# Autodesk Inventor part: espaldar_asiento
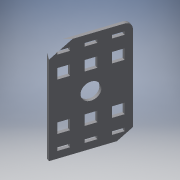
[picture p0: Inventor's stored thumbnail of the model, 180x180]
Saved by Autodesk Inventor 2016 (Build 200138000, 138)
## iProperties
Created: 2017-06
Part Number: espaldar_asiento
Material: Generic
Document SubType Name: Modeling
Designer: laboratorioesan
Density: 1 g/cm^3
Appearance: Default
Author: laboratorioesan
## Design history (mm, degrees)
sketch "Sketch1"
  geometry: L1 (0, 0)-(490, 0) reference; L2 (490, 0)-(490, 18.5) reference; L3 (0, 18.5)-(490, 18.5) reference; L4 (0, 0)-(0, 18.5) reference; L5 (854, -205.5)-(854, -75.5) reference; L6 (872.5, -75.5)-(872.5, -205.5) reference; L7 (872.5, -75.5)-(854, -75.5) reference; L8 (854, -205.5)-(854, -75.5) reference; L9 (872.5, -205.5)-(854, -205.5) reference; L10 (490, 18.5)-(613.607, 398.923); L11 (613.607, 398.923)-(631.201, 393.206); L12 (631.201, 393.206)-(507.595, 12.783); L13 (490, 18.5)-(507.595, 12.783)
  constraints: 8 end point, 3 perpendicular
  dimensions: "d0" = 18.5 distance of L10.end L11.end; "d1" = 18 deg angle of L2 L10; "d2" = 400 distance of L2.end L10.end
extrude "Extrusion1" new body sketch "Sketch1" distance "d3" = 600; taper "d4" = 0 deg
fillet "Fillet1" dims "d5" = 40
sketch "Sketch2"
  geometry: L1 (40, 400)-(560, 400) reference; L2 (0, 0)-(0, 360) reference; L3 (0, 0)-(600, 0) reference; L4 (600, 360)-(600, 0) reference; L5 (40, 360)-(58.5, 360); L6 (58.5, 360)-(58.5, 300); L7 (58.5, 300)-(40, 300); L8 (40, 300)-(40, 360); L9 (40, 230)-(58.5, 230); L10 (58.5, 230)-(58.5, 170); L11 (58.5, 170)-(40, 170); L12 (40, 170)-(40, 230); L13 (40, 100)-(58.5, 100); L14 (58.5, 100)-(58.5, 40); L15 (58.5, 40)-(40, 40); L16 (40, 40)-(40, 100); L17 (300, 400)-(300, 360); L18 (541.5, 170)-(560, 170); L19 (541.5, 230)-(541.5, 170); L20 (560, 170)-(560, 230); L21 (560, 230)-(541.5, 230); L22 (541.5, 300)-(560, 300); L23 (541.5, 360)-(541.5, 300); L24 (560, 300)-(560, 360); L25 (560, 360)-(541.5, 360); L26 (541.5, 100)-(541.5, 40); L27 (541.5, 40)-(560, 40); L28 (560, 40)-(560, 100); L29 (560, 100)-(541.5, 100); A1 r 40 centre (560, 360) between (600, 360) and (560, 400) reference; A2 r 40 centre (40, 360) between (40, 400) and (0, 360) reference; 2 further points
  constraints: 50 end point, 13 symmetric about line, 6 parallel, 4 point on line, 3 horizontal, 3 perpendicular, 1 midpoint, 1 vertical
  dimensions: "d6" = 18.5 distance of L6.end L7.end; "d7" = 60 distance of L5.end L6.end; "d8" = 40 distance between parallel lines of L1 L5; "d9" = 60 distance of L9.end L10.end; "d10" = 60 distance of L13.end L14.end; "d11" = 70 distance between parallel lines of L7 L9; "d12" = 70 distance between parallel lines of L13 L11
extrude "Extrusion2" cut sketch "Sketch2" distance "d13" = 18.5; taper "d14" = 0 deg
sketch "Sketch3"
  geometry: L1 (58.5, 300)-(40, 300) reference; L2 (40, 300)-(40, 360) reference; L3 (40, 360)-(58.5, 360) reference; L4 (58.5, 360)-(58.5, 300) reference; L5 (560, 100)-(560, 40) reference; L6 (560, 40)-(541.5, 40) reference; L7 (541.5, 40)-(541.5, 100) reference; L8 (541.5, 100)-(560, 100) reference; L9 (560, 360)-(560, 300) reference; L10 (560, 300)-(541.5, 300) reference; L11 (541.5, 300)-(541.5, 360) reference; L12 (541.5, 360)-(560, 360) reference; L13 (560, 230)-(560, 170) reference; L14 (560, 170)-(541.5, 170) reference; L15 (541.5, 170)-(541.5, 230) reference; L16 (541.5, 230)-(560, 230) reference; L17 (58.5, 170)-(40, 170) reference; L18 (40, 170)-(40, 230) reference; L19 (40, 230)-(58.5, 230) reference; L20 (58.5, 230)-(58.5, 170) reference; L21 (58.5, 100)-(58.5, 40) reference; L22 (58.5, 40)-(40, 40) reference; L23 (40, 40)-(40, 100) reference; L24 (40, 100)-(58.5, 100) reference; L25 (0, 0)-(0, 360) reference; L26 (600, 0)-(0, 0) reference; L27 (600, 360)-(600, 0) reference; L28 (560, 400)-(40, 400) reference; L29 (128.5, 360)-(188.5, 360); L30 (188.5, 360)-(188.5, 300); L31 (188.5, 300)-(128.5, 300); L32 (128.5, 300)-(128.5, 360); L33 (128.5, 230)-(188.5, 230); L34 (188.5, 230)-(188.5, 170); L35 (188.5, 170)-(128.5, 170); L36 (128.5, 170)-(128.5, 230); L37 (128.5, 100)-(188.5, 100); L38 (188.5, 100)-(188.5, 40); L39 (188.5, 40)-(128.5, 40); L40 (128.5, 40)-(128.5, 100); L41 (471.5, 230)-(411.5, 230); L42 (411.5, 230)-(411.5, 170); L43 (411.5, 170)-(471.5, 170); L44 (471.5, 170)-(471.5, 230); L45 (471.5, 300)-(411.5, 300); L46 (411.5, 300)-(411.5, 360); L47 (411.5, 360)-(471.5, 360); L48 (471.5, 360)-(471.5, 300); L49 (471.5, 100)-(411.5, 100); L50 (411.5, 100)-(411.5, 40); L51 (411.5, 40)-(471.5, 40); L52 (471.5, 40)-(471.5, 100); C1 r 50 at (300, 200); A1 r 40 centre (40, 360) between (40, 400) and (0, 360) reference; A2 r 40 centre (560, 360) between (600, 360) and (560, 400) reference; 3 further points
  constraints: 48 end point, 14 point on line, 12 parallel, 6 horizontal, 6 perpendicular, 2 midpoint, 1 centre point
  dimensions: "d15" = 60 distance of L30.end L31.end; "d16" = 60 distance of L43.end L42.end; "d17" = 70 distance of L3.end L29.start; "d18" = 70 distance of L47.end L11.end; "d21" = 100 diameter of C1
extrude "Extrusion3" cut sketch "Sketch3" distance "d22" = 18.5; taper "d23" = 0 deg
body "Solid1"
node "Reference1"
node "Reference2"
node "Reference3"
node "Projected Loop1"
node "Projected Loop2"
